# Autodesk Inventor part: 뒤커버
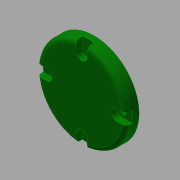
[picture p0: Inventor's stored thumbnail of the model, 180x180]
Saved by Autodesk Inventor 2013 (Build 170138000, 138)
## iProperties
Created: 2019-01
Part Number: 뒤커버
Material: 알루미늄 6061
Document SubType Name: Modeling
Designer: mduedu
Density: 1 g/cm^3
Author: mduedu
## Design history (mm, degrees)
sketch "스케치1"
  geometry: L1 (0, 0)-(9, 0); L2 (9, 0)-(9, 32); L3 (9, 32)-(0, 32); L4 (0, 32)-(0, 0); L5 (9, 0)-(12, 0); L6 (12, 0)-(12, 20); L7 (12, 20)-(9, 20); L8 (9, 20)-(9, 0)
  constraints: 16 end point, 4 parallel, 2 horizontal, 2 perpendicular
  dimensions: "d0" = 12 distance between parallel lines of L6 L4; "d2" = 64 diameter of L3 L1; "d3" = 40 diameter of L7 L5; "d4" = 3 distance between parallel lines of L6 L2
revolve "회전1" sketch "스케치1" stored, may be unused: angle "d5" = 90 deg
sketch "스케치4"
  geometry: C1 r 15 at (0, 0); 1 further point
  constraints: 1 centre point, 1 coincident
  dimensions: "d24" = 30 diameter of C1
extrude "돌출1" cut sketch "스케치4" distance "d25" = 6; taper "d26" = 0 deg
fillet "모깎기4" dims "d27" = 3
fillet "모깎기3" dims "d18" = 3
chamfer "모따기2" distance "d28" = 1; stored, may be unused: second distance "d29" = 2, angle "d30" = 45 deg
sketch "스케치3" dims "d19" = 50
  geometry: 6 further points
  constraints: 2 vertical alignment, 1 coincident, 7 other
  dimensions: "d22" = 360 deg dimension on point (0, 0) point (0, 25) (derived)
sketch "스케치5"
  geometry: 4 further points
  constraints: 4 other
hole "구멍1" sketch "스케치5" at (-25, 0), (0, -25), (25, 0), (0, 25) diameter "d31" = 4.5; stored, may be unused: countersink angle "d35" = 90 deg, drill point angle "d37" = 0 deg; dims "d32" = 6, "d33" = 8, "d34" = 4.6, "d36" = 8
sketch "스케치6"
  geometry: L1 (-4, 0)-(-4, 6.749); L2 (4, 0)-(4, 6.749); A1 r 4 centre (0, 0) between (0, 4) and (-4, 0) reference; A2 r 32 centre (0, -25) between (-4, 6.749) and (4, 6.749) reference; A3 r 4 centre (0, 0) between (-4, 0) and (4, 0); A4 r 32 centre (0, -25) between (4, 6.749) and (-4, 6.749); A5 r 4 centre (0, 0) between (4, 0) and (-4, 0); 1 further point
  constraints: 10 point on circle, 4 end point, 3 centre point, 2 coincident, 2 tangent, 1 parallel, 1 vertical
extrude "돌출2" cut sketch "스케치6" stored distance "d38" = 10; taper "d39" = 0 deg
node "솔리드1"
pattern_circular "원형 패턴1" dims angle "d41" = 360 deg
